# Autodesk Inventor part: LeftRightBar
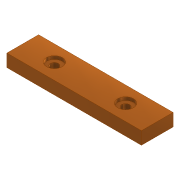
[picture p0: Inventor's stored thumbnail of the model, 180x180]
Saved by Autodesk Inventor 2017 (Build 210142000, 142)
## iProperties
Part Number: LeftRightBar
Material: ゴールド
Document SubType Name: Modeling
Designer: kyushu-hep
Density: 19.3 g/cm^3
Appearance: メタル 1600F 熱
Author: kyushu-hep
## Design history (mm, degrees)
sketch "スケッチ1"
  geometry: L1 (20.301, 16.049)-(-64.699, 16.049); L2 (-64.699, 16.049)-(-64.699, 8.049); L3 (-64.699, 8.049)-(20.301, 8.049); L4 (20.301, 8.049)-(20.301, 16.049); 1 further point
  constraints: 8 end point, 2 parallel, 1 horizontal, 1 perpendicular
  dimensions: "d0" = 85 distance of L3.end L2.end; "d1" = 8 distance of L1.end L2.end
extrude "押し出し1" new body sketch "スケッチ1" distance "d2" = 20; taper "d3" = 0 deg
sketch "スケッチ2"
  geometry: L1 (0, 0)-(0, 20) reference; L2 (85, 0)-(85, 20) reference; L3 (0, 20)-(85, 20) reference; C1 r 5 at (20, 10); C2 r 5 at (65, 10); 1 further point
  constraints: 2 centre point
  dimensions: "d13" = 10 diameter of C1; "d14" = 20 distance from line of L1 C1.centre; "d15" = 10 diameter of C2; "d16" = 20 distance from line of L2 C2.centre; "d25" = 10 distance from line of C1.centre L3; "d26" = 10 distance from line of C2.centre L3
extrude "押し出し2" cut sketch "スケッチ2" distance "d17" = 2; taper "d18" = 0 deg
sketch "スケッチ3"
  geometry: L1 (-20, -10)-(-20, 10) reference; L2 (65, -10)-(65, 10) reference; L3 (-20, 10)-(65, 10) reference; C1 r 2.5 at (0, 0); C2 r 2.5 at (45, 0); 1 further point
  constraints: 2 centre point
  dimensions: "d19" = 5 diameter of C1; "d20" = 5 diameter of C2; "d21" = 20 distance from line of L1 C1.centre; "d22" = 20 distance from line of L2 C2.centre; "d23" = 10 distance from line of L3 C2.centre; "d24" = 10 distance from line of L3 C1.centre
extrude "押し出し3" cut sketch "スケッチ3" distance "d27" = 6; taper "d28" = 0 deg
node "ソリッド1"
